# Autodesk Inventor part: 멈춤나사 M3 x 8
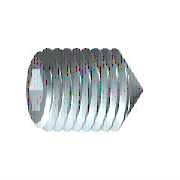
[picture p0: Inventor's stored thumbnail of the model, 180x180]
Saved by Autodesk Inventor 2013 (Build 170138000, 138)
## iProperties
IsCustomPart: 1
Created: 2012-02
Part Number: 멈춤나사 M3 x 8
Material: 강철, 연강
Description: 6각 소켓 머리 없는 멈춤 나사
Document SubType Name: Modeling
Standard: KS B 1028
Designer: test
Standards Organization: KS
Language: ko-KR
Size Designation: 원추점 M3x8
Categories: <MemberInstance><Categories><Category DisplayName="조임쇠" InternalName="e4da775c-781d-43d5-af7c-5136215cf5a6" Mnemonic="FSTN"><Category DisplayName="볼트" InternalN
Density: 1 g/cm^3
Author: test
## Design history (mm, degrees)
sketch "스케치1"
  geometry: L1 (0, 0)-(5.5, 0); L2 (8, 0.866)-(8, 1.5); L3 (8, 1.5)-(0, 1.5); L4 (8, 0.866)-(6, 0.866); L5 (6, 0.866)-(5.5, 0); L6 (0, -0.3)-(0, 1.8) reference; L7 (0, 1.5)-(0, 0)
  constraints: 13 end point, 3 parallel, 1 collinear, 1 perpendicular, 1 point on line
  dimensions: "d0" = 2 distance of L2.start L4.end (= INTI); "d1" = 60 deg angle of L5 L1; "d2" = 3 diameter of L3 L1 (= NND); "d3" = 1.73205 diameter of L4 L1 (= 1.1547 x SW); "d5" = 8 distance from line of L2 L3.end (= NLG)
revolve "본체" sketch "스케치1" stored, may be unused: angle "d6" = 90 deg
sketch "스케치2"
  geometry: L1 (-0.433, 0.75)-(0.433, 0.75); L2 (0.433, 0.75)-(0.866, 0); L3 (0.866, 0)-(0.433, -0.75); L4 (0.433, -0.75)-(-0.433, -0.75); L5 (-0.433, -0.75)-(-0.866, 0); L6 (-0.866, 0)-(-0.433, 0.75); 3 further points
  constraints: 12 end point, 1 coincident, 1 horizontal, 13 other
extrude "슬롯" join sketch "스케치2" taper "d7" = 0 deg; stored distance "d21" = 10
workaxis "Work Axis1"
workplane "Work Plane1"
sketch "스케치4"
  geometry: L1 (0, 0.15)-(-1.35, 1.5) reference; L2 (0, -0.15)-(-1.35, -1.5) reference; L3 (-1.35, -1.5)-(0.15, 0); L4 (-1.35, 1.5)-(0.15, 0); 2 further points
  constraints: 4 end point, 1 coincident, 1 collinear, 1 horizontal alignment
body "Solid1"
feature "스레드" dims "d12" = 8 (= NLG), "d13" = 0
chamfer "모따기1" distance "d8" = 1.35 (computed from NND, SPD, FAWI); stored, may be unused: angle "d9" = 45 deg (= FAWI), second distance "d34" = 1.35 (computed from NND, SPD, FAWI)
chamfer "모따기2" distance "d10" = 0.30673 (= -0.5 x GD1 + 0.5 x NND); stored, may be unused: angle "d11" = 45 deg (= FAWI), second distance "d35" = 0.30673 (= -0.5 x GD1 + 0.5 x NND)
other parameters: "NND" = 3 [user parameter; used in 5 equation terms], "NLG" = 8 [user parameter; used in 2 equation terms], "INTI" = 2 [user parameter; used in 1 equation term], "FAWI" = 45 deg [user parameter; used in 4 equation terms], "SW" = 1.5 [user parameter; used in 2 equation terms], "GD1" = 2.38655 (= THREADDIA - 1.2269 x PTC) [user parameter; used in 2 equation terms], "d4" = 0, "FAWI1" = 45 deg [user parameter], "SPD" = 0.3 [user parameter; used in 2 equation terms], "d36" = 0, "d37" = 0, "GUL" = 0.30673 (= 0.61345 x PTC) [user parameter], "TOA" = 30 deg [user parameter], "THREADDIA" = 3 [user parameter; used in 1 equation term], "PTC" = 0.5 [user parameter; used in 4 equation terms], "GAL" = 0.30673 (= 0.61345 x PTC) [user parameter], "E0" = 1.7325 (= 1.155 x SW) [user parameter]
